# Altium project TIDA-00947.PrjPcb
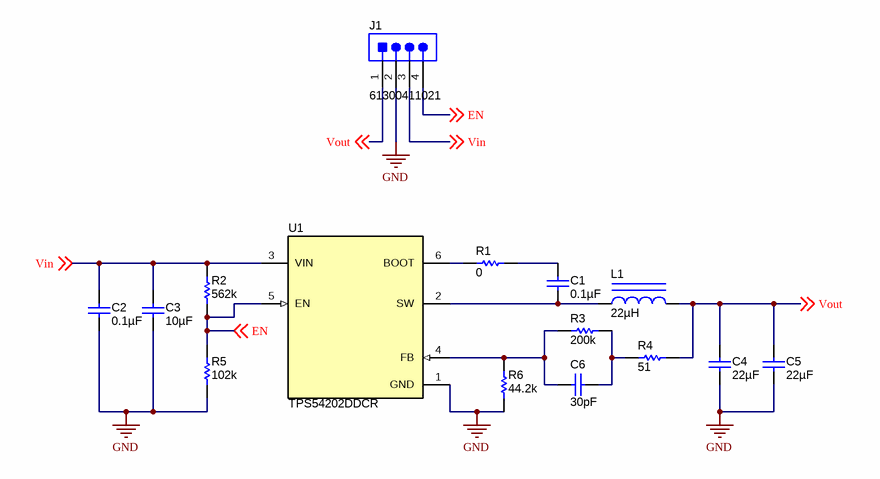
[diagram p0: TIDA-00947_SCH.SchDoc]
TID: TIDA-00947; TechSupport: http://www.ti.com/support; SCH_Rev: E1; PRJ_Title: 3.3V 1A DC/DC Modules with Low EMI and High Efficiency; PRJ_Number: TIDA-00947; PRJ_Engineer: Kong / Stauder; PRJ_Customer: Public Release; PCB_Rev: E1; PCB_Layout: Stauder; EVM_Orderable: N/A; CopyrightYear: 2016
2 sheets, 19 parts. Net scope: global (net labels, ports and power ports of the same name join across sheets).
Board file: TIDA-00947_PCB.PcbDoc
Sheets:
  TIDA-00947_SCH.SchDoc
  TIDA-00947_EVM_Hardware.SchDoc

## Sheet TIDA-00947_SCH.SchDoc
size 431 x 279 mm; Date: Not shown in title block; ApprovedBy: Not shown in title block; CheckedBy: Not shown in title block; Author: Not shown in title block; CompanyName: Not shown in title block; Engineer: Not shown in title block; Organization: Not shown in title block; Address1: Not shown in title block; Address2: Not shown in title block; Address3: Not shown in title block; Address4: Not shown in title block; DocumentNumber: 1; Revision: Use project parameter SCH_Rev; SheetNumber: 2; SheetTotal: 3; PageSetup: Record=PageOptions¦CenterHorizontal=True¦CenterVertical=True¦PrintScale=1.00¦XCorrection=1.00¦YCorrection=1.00¦PrintKind=0¦BorderSize=5000000¦LeftOffset=0¦BottomOffset=0¦Orientation=2¦PaperLength=1000¦PaperWidth=1000¦Scale=100¦PaperSource=15¦PrintQuality=600¦MediaType=1¦DitherType=10¦PaperKind=Letter¦PrintScaleMode=1

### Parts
C1  ValueDisplayed: 0.1µF  [0603]  (hidden comment: GRM188R70J104KA01D)
C2  ValueDisplayed: 0.1µF  [0603]  (hidden comment: 885012206071)
C3  ValueDisplayed: 10µF  [1206]  (hidden comment: GMK316AB7106KL)
C4  ValueDisplayed: 22µF  [0805_HV]  (hidden comment: GRM21BZ71A226ME15L)
C5  ValueDisplayed: 22µF  [0805_HV]  (hidden comment: GRM21BZ71A226ME15L)
C6  ValueDisplayed: 30pF  [0603]  (hidden comment: GRM1885C1H300JA01D)
J1  61300411021  [Wurth_61300411021]
L1  ValueDisplayed: 22µH  [THPC6045MF]  (hidden comment: THPC6045MF-220M)
R1  ValueDisplayed: 0  [0603]  (hidden comment: CRCW06030000Z0EA)
R2  ValueDisplayed: 562k  [0603]  (hidden comment: CRCW0603562KFKEA)
R3  ValueDisplayed: 200k  [0603]  (hidden comment: CRCW0603200KFKEA)
R4  ValueDisplayed: 51  [0603]  (hidden comment: CRCW060351R0JNEA)
R5  ValueDisplayed: 102k  [0603]  (hidden comment: CRCW0603102KFKEA)
R6  ValueDisplayed: 44.2k  [0603]  (hidden comment: CRCW060344K2FKEA)
U1  TPS54202DDCR  [DDC0006A_N]

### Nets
GND: C2.2 C3.2 C4.2 C5.2 J1.2 R5.1 R6.1 U1.1(GND)
EN: J1.4 R2.1 R5.2 U1.5(EN) ; off-sheet EN
Vin: C2.1 C3.1 J1.3 R2.2 U1.3(VIN) ; off-sheet Vin
Vout: C4.1 C5.1 J1.1 L1.2 R4.2 ; off-sheet Vout
NetC1_1: C1.1 R1.2
NetC1_2: C1.2 L1.1 U1.2(SW)
NetC6_1: C6.1 R3.2 R4.1
NetC6_2: C6.2 R3.1 R6.2 U1.4(FB)
NetR1_1: R1.1 U1.6(BOOT)

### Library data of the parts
C1 = GRM188R70J104KA01D: CAP, CERM, 0.1 µF, 6.3 V, +/- 10%, X7R, 0603; Manufacturer: MuRata; Polarized: N; CompType: Capacitor; Value: 0.1uF; U/M: EA; Cap_F: 0.0000001; Tolerance_%: 10; Value1: Unknown; VDC_V: 6.3; Value2: 6.3V; TaMin_C: -55; TaMax_C: 125; AEC Category: Q200
C2 = 885012206071: CAP, CERM, 0.1 µF, 25 V, +/- 10%, X7R, 0603; Manufacturer: Wurth Elektronik; Polarized: N; CompType: Capacitor; Value: 0.1uF; U/M: EA; Cap_F: 0.0000001; Tolerance_%: 10; Value1: Unknown; VDC_V: 25; Value2: 25V; TaMin_C: -55; TaMax_C: 125; AEC Category: Q200
C3 = GMK316AB7106KL: CAP, CERM, 10 µF, 35 V, +/- 10%, X7R, 1206; Manufacturer: Taiyo Yuden; Polarized: N; CompType: Capacitor; Value: 10uF; U/M: EA; Cap_F: 0.00001; Tolerance_%: 10; Value1: Unknown; VDC_V: 35; Value2: 35V; TaMin_C: -55; TaMax_C: 125; AEC Category: Q200
C4 C5 = GRM21BZ71A226ME15L: CAP, CERM, 22 µF, 10 V, +/- 20%, X7R, 0805; Manufacturer: MuRata; Polarized: N; CompType: Capacitor; Value: 22uF; U/M: EA; Cap_F: 0.000022; Tolerance_%: 20; Value1: Unknown; VDC_V: 10; Value2: 10V; TaMin_C: -55; TaMax_C: 125; Cap_Case: 0805; AEC Category: Q200
C6 = GRM1885C1H300JA01D: CAP, CERM, 30 pF, 50 V, +/- 5%, C0G/NP0, 0603; Manufacturer: MuRata; Polarized: N; CompType: Capacitor; Value: 30pF; U/M: EA; Cap_F: 0.00000000003; Tolerance_%: 5; Value1: Unknown; VDC_V: 50; Value2: 50V; TaMin_C: -55; TaMax_C: 125; AEC Category: Q200
J1 = 61300411021: Header, 2.54 mm, 4x1, Gold, R/A, TH; Manufacturer: Wurth Elektronik; SymbolCreator: a0412235; Pitch_mm: 2.54; Gender: Male; Shrouded: N; Row_Count: 1
L1 = THPC6045MF-220M: Inductor, Ferrite, 22 µH, 1.9 A, 0.096 ohm, SMD; Manufacturer: Tai-Tech; Value: 22uH; Ind_H: 22.0E-6; Imax_A: 1.9; Irms: 1.9A @ 40C rise; Isat: 2.7A @ 30% inductance drop; DCR_ohm: 0.096; Value2: 1.9A; AEC Category: Q200; AEC Qualified: N
R1 = CRCW06030000Z0EA: RES, 0, 5%, 0.1 W, 0603; Manufacturer: Vishay-Dale; CompType: Resistor; Value: 0; Value_Code: 0000; Tolerance_%: 5; Power_W: 0.1; Value2: 0.1W; VDC_V: 75; TempCo: 200 ppm/C; EIA_Code: E24; U/M: EA; AEC Category: Q200
R2 = CRCW0603562KFKEA: RES, 562 k, 1%, 0.1 W, 0603; Manufacturer: Vishay-Dale; CompType: Resistor; Value: 562k; Res_ohm: 562000; Tolerance_%: 1; Power_W: 0.1; Value2: 0.1W; VDC_V: 75; TempCo: 100 ppm/C; EIA_Code: E96; U/M: EA; AEC Category: Q200
R3 = CRCW0603200KFKEA: RES, 200 k, 1%, 0.1 W, 0603; Manufacturer: Vishay-Dale; CompType: Resistor; Value: 200k; Res_ohm: 200000; Tolerance_%: 1; Power_W: 0.1; Value2: 0.1W; VDC_V: 75; TempCo: 100 ppm/C; EIA_Code: E96; U/M: EA; AEC Category: Q200
R4 = CRCW060351R0JNEA: RES, 51, 5%, 0.1 W, 0603; Manufacturer: Vishay-Dale; CompType: Resistor; Value: 51; Value_Code: 51R0; Tolerance_%: 5; Power_W: 0.1; Value2: 0.1W; VDC_V: 75; TempCo: 200 ppm/C; EIA_Code: E24; U/M: EA; AEC Category: Q200
R5 = CRCW0603102KFKEA: RES, 102 k, 1%, 0.1 W, 0603; Manufacturer: Vishay-Dale; CompType: Resistor; Value: 102k; Res_ohm: 102000; Tolerance_%: 1; Power_W: 0.1; Value2: 0.1W; VDC_V: 75; TempCo: 100 ppm/C; EIA_Code: E96; U/M: EA; AEC Category: Q200
R6 = CRCW060344K2FKEA: RES, 44.2 k, 1%, 0.1 W, 0603; Manufacturer: Vishay-Dale; CompType: Resistor; Value: 44.2k; Res_ohm: 44200; Value_Code: 44k2; Tolerance_%: 1; Power_W: 0.1; Value2: 0.1W; VDC_V: 75; TempCo: 100 ppm/C; EIA_Code: E96; U/M: EA; AEC Category: Q200
U1 = TPS54202DDCR: 4.5-V TO 28-V INPUT, 2-A OUTPUT, EMI FRIENDLY SYNCHRONUOUS STEP-DOWN CONVERTOR, DDC0006A; Alternate PartNumber: TPS54202DDCT; Manufacturer: Texas Instruments; SymbolCreator: a0411947; CompType: IC; U/M: EA

## Sheet TIDA-00947_EVM_Hardware.SchDoc
size 431 x 279 mm; Date: Not shown in title block; ApprovedBy: Not shown in title block; CheckedBy: Not shown in title block; Author: Not shown in title block; CompanyName: Not shown in title block; Engineer: Not shown in title block; Organization: Not shown in title block; Address1: Not shown in title block; Address2: Not shown in title block; Address3: Not shown in title block; Address4: Not shown in title block; DocumentNumber: 1; Revision: Use project parameter SCH_Rev; SheetNumber: 3; SheetTotal: 3; PageSetup: Record=PageOptions¦CenterHorizontal=True¦CenterVertical=True¦PrintScale=1.00¦XCorrection=1.00¦YCorrection=1.00¦PrintKind=0¦BorderSize=5000000¦LeftOffset=0¦BottomOffset=0¦Orientation=2¦PaperLength=1000¦PaperWidth=1000¦Scale=100¦PaperSource=15¦PrintQuality=600¦MediaType=1¦DitherType=10¦PaperKind=Letter¦PrintScaleMode=1
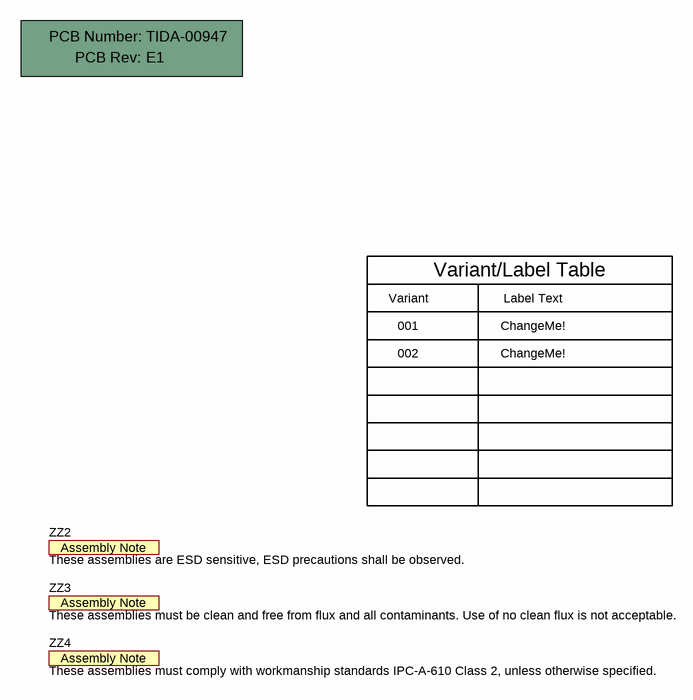
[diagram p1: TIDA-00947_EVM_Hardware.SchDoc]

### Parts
!PCB1  Printed Circuit Board  (value not drawn)  (mechanical)
ZZ2  These assemblies are ESD sensitive, ESD precautions shall be observed.  [AssemblyNote]  (no BOM)
ZZ3  These assemblies must be clean and free from flux and all contaminants. Use of no clean flux is not acceptable.  [AssemblyNote]  (no BOM)
ZZ4  These assemblies must comply with workmanship standards IPC-A-610 Class 2, unless otherwise specified.  [AssemblyNote]  (no BOM)

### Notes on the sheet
- Variant
- Variant/Label Table
- Label Text
- 001
- 002
- ChangeMe!

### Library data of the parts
!PCB1 = PCB: Manufacturer: Any; PartNumber: TIDA-00947; SymbolCreator: a0412235
ZZ2-ZZ4 = AssemblyNote: SymbolCreator: codlsc

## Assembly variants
001: all parts fitted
